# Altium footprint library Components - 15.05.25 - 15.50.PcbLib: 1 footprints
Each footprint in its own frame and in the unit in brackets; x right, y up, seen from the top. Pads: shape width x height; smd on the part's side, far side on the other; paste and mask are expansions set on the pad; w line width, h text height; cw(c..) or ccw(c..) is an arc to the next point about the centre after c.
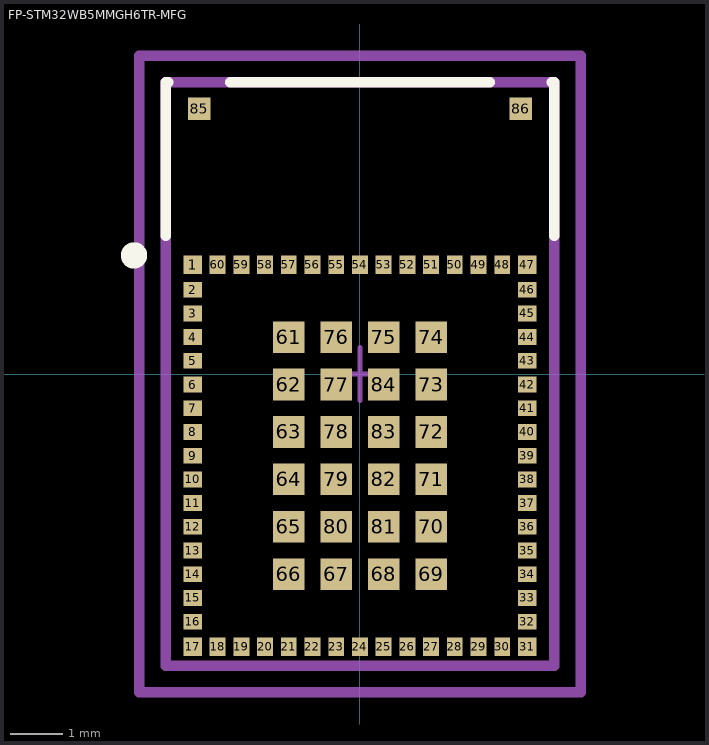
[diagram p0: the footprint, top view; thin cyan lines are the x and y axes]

## FP-STM32WB5MMGH6TR-MFG [mm]
pads (86):
  rect 0.35x0.35 smd paste+0 mask+0: 1(-3.175,2.075) 17(-3.175,-5.175) 31(3.175,-5.175) 47(3.175,2.075)
  rect 0.35x0.3 smd paste+0 mask+0: 2(-3.175,1.6) 3(-3.175,1.15) 4(-3.175,0.7) 5(-3.175,0.25) 6(-3.175,-0.2) 7(-3.175,-0.65) 8(-3.175,-1.1) 9(-3.175,-1.55) 10(-3.175,-2) 11(-3.175,-2.45) 12(-3.175,-2.9) 13(-3.175,-3.35) 14(-3.175,-3.8) 15(-3.175,-4.25) 16(-3.175,-4.7) 32(3.175,-4.7) 33(3.175,-4.25) 34(3.175,-3.8) 35(3.175,-3.35) 36(3.175,-2.9) 37(3.175,-2.45) 38(3.175,-2) 39(3.175,-1.55) 40(3.175,-1.1) 41(3.175,-0.65) 42(3.175,-0.2) 43(3.175,0.25) 44(3.175,0.7) 45(3.175,1.15) 46(3.175,1.6)
  rect 0.3x0.35 smd paste+0 mask+0: 18(-2.7,-5.175) 19(-2.25,-5.175) 20(-1.8,-5.175) 21(-1.35,-5.175) 22(-0.9,-5.175) 23(-0.45,-5.175) 24(0,-5.175) 25(0.45,-5.175) 26(0.9,-5.175) 27(1.35,-5.175) 28(1.8,-5.175) 29(2.25,-5.175) 30(2.7,-5.175) 48(2.7,2.075) 49(2.25,2.075) 50(1.8,2.075) 51(1.35,2.075) 52(0.9,2.075) 53(0.45,2.075) 54(0,2.075) 55(-0.45,2.075) 56(-0.9,2.075) 57(-1.35,2.075) 58(-1.8,2.075) 59(-2.25,2.075) 60(-2.7,2.075)
  rect 0.6x0.6 smd paste+0 mask+0: 61(-1.35,0.7) 62(-1.35,-0.2) 63(-1.35,-1.1) 64(-1.35,-2) 65(-1.35,-2.9) 66(-1.35,-3.8) 67(-0.45,-3.8) 68(0.45,-3.8) 69(1.35,-3.8) 70(1.35,-2.9) 71(1.35,-2) 72(1.35,-1.1) 73(1.35,-0.2) 74(1.35,0.7) 75(0.45,0.7) 76(-0.45,0.7) 77(-0.45,-0.2) 78(-0.45,-1.1) 79(-0.45,-2) 80(-0.45,-2.9) 81(0.45,-2.9) 82(0.45,-2) 83(0.45,-1.1) 84(0.45,-0.2)
  rect 0.43x0.43 smd paste+0 mask+0: 85(-3.05,5.035) 86(3.05,5.035)
Top Overlay:
  circle w0.25: c-4.287,2.25 r0.125
  lines w0.2: -3.688,2.625 -3.688,5.537 -3.64,5.537 ; -2.46,5.537 2.46,5.537 ; 3.64,5.537 3.688,5.537 3.688,2.625
Top Assembly:
  lines w0.2: -4.187,-6.038 -4.187,6.038 4.187,6.038 4.187,-6.038 -4.187,-6.038
  text ".Designator" at 0,0.188 h1
Top 3D Body:
  lines w0.2: -3.688,-5.537 -3.688,5.537 3.688,5.537 3.688,-5.537 -3.688,-5.537
Top Courtyard:
  lines w0.2: -4.187,-6.038 -4.187,6.038 4.187,6.038 4.187,-6.038 -4.187,-6.038
Top Component Center:
  lines w0.1: -0.5,0 0.5,0 ; 0,-0.5 0,0.5
3D body "UNK_STMicroelectronics_STM32WB5MMGH6TR_eec.STEP": height 0.25, standoff 0, extent -4.187,-6.038 4.187,6.038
